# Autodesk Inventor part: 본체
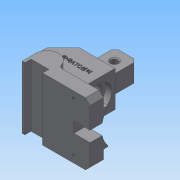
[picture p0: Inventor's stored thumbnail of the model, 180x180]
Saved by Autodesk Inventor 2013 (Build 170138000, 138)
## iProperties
Created: 2016-11
Part Number: 본체
Material: 일반
Document SubType Name: Modeling
Designer: Administrator
Density: 1 g/cm^3
Author: Administrator
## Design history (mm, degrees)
sketch "스케치1"
  geometry: L1 (0, 0)-(-58, 0); L2 (-58, 0)-(-58, -30); L3 (-58, -30)-(32, -30); L4 (-40, 18)-(0, 18); L5 (0, 18)-(0, 0); L6 (32, -22)-(0, -22); L7 (0, -22)-(0, 0); L8 (32, -30)-(32, -22); L9 (-58, 0)-(-40, 18); L10 (-58, 0)-(13.121, 0)
  constraints: 20 end point, 2 horizontal, 2 parallel, 2 perpendicular
  dimensions: "d0" = 58 distance of L1.start L1.end; "d1" = 30 distance of L1.end L2.end; "d2" = 90 distance of L2.end L3.end; "d8" = 8 distance between parallel lines of L3 L6; "d9" = 45 deg angle of L10 L9; "d10" = 18 distance between parallel lines of L1 L4; "d11" = 58 distance from line of L1.end L5
extrude "돌출1" new body sketch "스케치1" stored distance "d12" = 40; taper "d13" = 0 deg
sketch "스케치2"
  geometry: L1 (32, -27)-(32, -42); L2 (32, -22)-(32, -30) reference; L3 (32, -42)-(-31, -42); L4 (-44, -27)-(-44, -42); L5 (-44, -42)-(-31, -42); L6 (-18, -27)-(32, -27); A1 r 13 centre (-31, -27) between (-18, -27) and (-44, -27); 1 further point
  constraints: 10 end point, 4 perpendicular, 2 point on circle, 1 centre point, 1 collinear, 1 point on line, 1 tangent, 1 vertical alignment
  dimensions: "d14" = 20 distance of L2.start L1.end; "d15" = 63 distance of L1.end L3.end; "d16" = 26 diameter of A1; "d17" = 15 distance from line of L3 A1.centre; "d19" = 15 distance between parallel lines of L3 L6
extrude "돌출2" join sketch "스케치2" distance "d20" = 15; taper "d21" = 0 deg
sketch "스케치3"
  geometry: L1 (-44, -27)-(-44, -42) reference; L2 (-44, -42)-(32, -42) reference; L3 (-41, -35)-(-21, -35); L4 (-21, -35)-(-21, -42); L5 (-21, -42)-(-41, -42); L6 (-41, -42)-(-41, -35); 1 further point
  constraints: 8 end point, 2 parallel, 1 horizontal, 1 perpendicular, 1 point on line
  dimensions: "d22" = 7 distance between parallel lines of L5 L3; "d24" = 20 distance between parallel lines of L6 L4; "d25" = 3 distance between parallel lines of L1 L6
extrude "돌출3" cut sketch "스케치3" stored distance "d26" = 15; taper "d27" = 0 deg
chamfer "모따기1" distance "d28" = 4; stored, may be unused: second distance "d29" = 2, angle "d30" = 45 deg
fillet "모깎기1" dims "d31" = 5
chamfer "모따기2" distance "d32" = 5; stored, may be unused: second distance "d33" = 2, angle "d34" = 45 deg
sketch "스케치4"
  geometry: L1 (76, 0)-(0, 0); L2 (0, 0)-(0, -40); L3 (0, -40)-(76, -40); L4 (76, -40)-(76, 0); 1 further point
  constraints: 8 end point, 2 parallel, 1 horizontal, 1 perpendicular
extrude "돌출4" join sketch "스케치4" distance "d35" = 12; taper "d36" = 0 deg
sketch "스케치5"
  geometry: L1 (0, 0)-(20, 0); L2 (20, 0)-(20, 7); L3 (20, 7)-(0, 7); L4 (0, 7)-(0, 0); 1 further point
  constraints: 8 end point, 2 parallel, 1 horizontal, 1 perpendicular
extrude "돌출5" cut sketch "스케치5" stored distance "d37" = 12; taper "d38" = 0 deg
sketch "스케치6"
  geometry: L1 (40, 40)-(40, 0) reference; L2 (10, 30)-(35, 30); L3 (35, 30)-(35, 10); L4 (35, 10)-(10, 10); L5 (10, 10)-(10, 30); 3 further points
  constraints: 8 end point, 2 midpoint, 2 parallel, 1 horizontal, 1 horizontal alignment, 1 perpendicular
  dimensions: "d39" = 20 distance between parallel lines of L4 L2; "d41" = 5 distance between parallel lines of L1 L3; "d42" = 25 distance between parallel lines of L5 L3
extrude "돌출6" join sketch "스케치6" distance "d43" = 30; taper "d44" = 0 deg
chamfer "모따기3" distance "d45" = 4; stored, may be unused: second distance "d46" = 2, angle "d47" = 45 deg
fillet "모깎기2" dims "d48" = 3
sketch "스케치7"
  geometry: L1 (-4, -4)-(0, 0) reference; L2 (-4, -27)-(-4, -4) reference; L3 (24, -30)-(-7, -30) reference; L4 (21, -27)-(21, -4) reference; L5 (17, 0)-(21, -4) reference; L6 (0, 0)-(17, 0) reference; C1 r 4 at (8.5, -14.684); A1 r 3 centre (-7, -27) between (-7, -30) and (-4, -27) reference; A2 r 3 centre (24, -27) between (21, -27) and (24, -30) reference; 1 further point
  constraints: 1 centre point
  dimensions: "d49" = 8 diameter of C1; "d50" = 12.5 distance from line of C1.centre L2
sketch "스케치8"
  geometry: L1 (40, -26)-(0, -26) reference; L2 (0, -30)-(40, -30) reference; C1 r 10 at (20, 0); 2 further points
  constraints: 1 centre point, 1 midpoint, 1 vertical alignment
  dimensions: "d51" = 20 diameter of C1; "d52" = 30 distance from line of L2 C1.centre
extrude "돌출7" cut sketch "스케치8" stored distance "d53" = 30; taper "d54" = 0 deg
sketch "스케치9"
  geometry: C1 r 10 at (20, 22) reference; C2 r 14.5 at (20, 22)
  constraints: 1 centre point, 1 coincident
  dimensions: "d55" = 29 diameter of C2
extrude "돌출8" cut sketch "스케치9" distance "d56" = 7; taper "d57" = 0 deg
chamfer "모따기4" distance "d58" = 1; stored, may be unused: second distance "d59" = 2, angle "d60" = 45 deg
sketch "스케치10"
  geometry: L1 (-4, -27)-(-4, -4) reference; L2 (5, -90)-(53, -90) reference; C1 r 4 at (8.5, -13); 1 further point
  constraints: 1 centre point
  dimensions: "d61" = 8 diameter of C1; "d62" = 12.5 distance from line of C1.centre L1; "d63" = 77 distance from line of L2 C1.centre
extrude "돌출9" cut sketch "스케치10" stored distance "d64" = 7; taper "d65" = 0 deg
chamfer "모따기5" distance "d66" = 1; stored, may be unused: second distance "d67" = 2, angle "d68" = 45 deg
fillet "모깎기3" dims "d69" = 3
sketch "스케치11"
  geometry: C1 r 29 at (20, 22); 1 further point
  constraints: 1 centre point, 1 coincident
  dimensions: "d70" = 58 diameter of C1
extrude "돌출10" cut sketch "스케치11" distance "d71" = 18; taper "d72" = 0 deg
sketch "스케치12"
  geometry: L1 (50, -15)-(-10, -15) reference; L2 (26, -15)-(14, -15); L3 (14, -15)-(14, 10); L4 (14, 10)-(26, 10); L5 (26, 10)-(26, -15); 2 further points
  constraints: 8 end point, 3 midpoint, 2 parallel, 1 coincident, 1 horizontal, 1 perpendicular
  dimensions: "d73" = 12 distance between parallel lines of L5 L3; "d75" = 25 distance between parallel lines of L2 L4
extrude "돌출11" cut sketch "스케치12" distance "d76" = 18; taper "d77" = 0 deg
node "작업 평면1"
sketch "스케치13"
  geometry: L1 (45.708, 0)-(45.708, -10) reference; L2 (40.708, -15)-(40.708, 20); 2 further points
  constraints: 2 end point, 1 parallel
  dimensions: "d79" = 18 distance from line of L1 point (27.708, -7.5); "d80" = 35 distance of L2.start L2.end; "d81" = 27.5 vertical distance of L2.end point (27.708, -7.5)
hole "구멍1" sketch "스케치13" at (27.708, -7.5) diameter "d82" = 3.242; stored, may be unused: countersink angle "d86" = 90 deg, drill point angle "d88" = 118 deg; dims "d83" = 49, "d84" = 4, "d85" = 2, "d87" = 50
sketch "스케치14"
  geometry: L1 (0, -19)-(0, 18) reference; L2 (0, 18)-(-40, 18) reference; 2 further points
  constraints: 1 other
  dimensions: "d89" = 25 distance from line of L1 point (-25, 0); "d90" = 18 distance from line of point (-25, 0) L2
feature "엠보싱1" sketch "스케치14" dims "d0" = 58, "d1" = 30, "d2" = 90, "d8" = 8, "d9" = 45 deg, "d10" = 18, "d11" = 58, "d14" = 20, "d15" = 63, "d16" = 26, "d17" = 15, "d19" = 15, "d91" = 0.5, "d92" = 0
node "솔리드1"
mirror "대칭1"
mirror "대칭2"
other parameters: "d78" = 0
